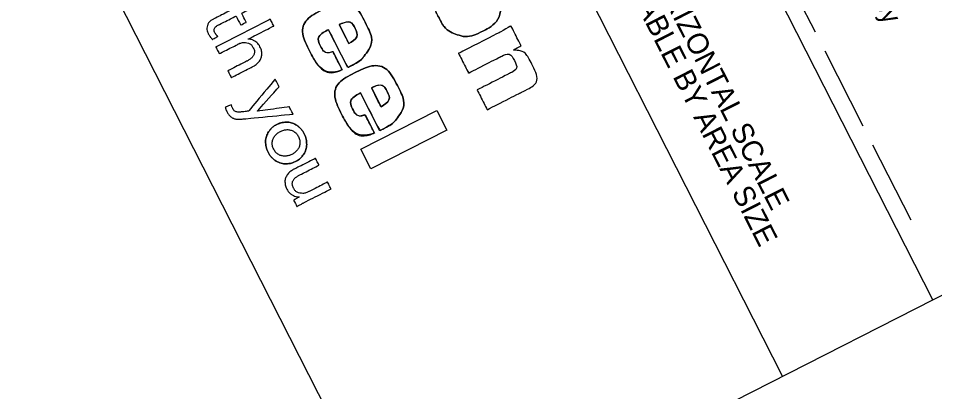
# Model space of a CAD drawing. Extents: x 152091 to 153435, y 1210118 to 1211616.
# Drawn here: x 152681.9 to 152812.3, y 1210201.4 to 1210254.5 of the extents above; entities that cross this region are included whole.
import ezdxf

# ---------------------------------------------------------------- set-up
doc = ezdxf.new("R2010")
doc.units = 0
for name, color, linetype in [('G-ANNO-BAR', 7, 'Continuous'), ('G-ANNO-STMP', 7, 'Continuous'), ('G-TTLB-LOGO', 7, 'Continuous'), ('G-TTLB-OTLN', 7, 'Continuous')]:
    doc.layers.add(name, color=color, linetype=linetype)

msp = doc.modelspace()

# ---------------------------------------------------------------- linework, layer by layer
at = {"layer": 'G-ANNO-STMP'}
for p, q in [((152789.88, 1210263.28), (152795.33, 1210252.59)), ((152796.69, 1210249.92), (152802.13, 1210239.22)), ((152803.49, 1210236.55), (152808.93, 1210225.85))]:
    msp.add_line(p, q, dxfattribs=at)
at = {"layer": 'G-TTLB-LOGO'}
for p, q in [((152728.79, 1210247.52), (152726.05, 1210252.91)), ((152727.59, 1210253.65), (152728.96, 1210250.95)), ((152726.7, 1210249.81), (152728.03, 1210247.19)), ((152732.16, 1210244.66), (152733.54, 1210241.96)), ((152733.36, 1210238.54), (152730.62, 1210243.92)), ((152730.68, 1210235.92), (152741.48, 1210241.42)), ((152731.27, 1210240.82), (152732.61, 1210238.21)), ((152741.48, 1210241.42), (152742.91, 1210238.61)), ((152742.91, 1210238.61), (152732.11, 1210233.11)), ((152732.11, 1210233.11), (152730.68, 1210235.92))]:
    msp.add_line(p, q, dxfattribs=at)
msp.add_lwpolyline([(152741.48, 1210241.42), (152742.91, 1210238.61), (152732.11, 1210233.11), (152730.68, 1210235.92), (152741.48, 1210241.42)], dxfattribs=at)
for points in [[(152749.56, 1210258.95), (152750.8, 1210256.51), (152750.54, 1210253.99), (152747.88, 1210252.64), (152746.79, 1210252.08), (152745.52, 1210251.83), (152744.35, 1210252.21), (152743.41, 1210252.53), (152742.48, 1210253.22), (152741.7, 1210254.76), (152740.85, 1210256.42), (152740.71, 1210257.7), (152741.04, 1210258.79), (152741.42, 1210260.08), (152742.43, 1210260.86), (152743.34, 1210261.32), (152745.65, 1210262.49), (152748.04, 1210261.93), (152749.56, 1210258.95)], [(152749.56, 1210258.95), (152750.8, 1210256.51), (152750.54, 1210253.99), (152747.88, 1210252.64), (152746.79, 1210252.08), (152745.52, 1210251.83), (152744.35, 1210252.21), (152743.41, 1210252.53), (152742.48, 1210253.22), (152741.7, 1210254.76), (152741.52, 1210255.1), (152741.38, 1210255.43), (152741.26, 1210255.74)], [(152713.57, 1210253.56), (152713.57, 1210253.56), (152712.91, 1210254.86), (152712.91, 1210254.86), (152712.91, 1210254.86), (152710.38, 1210253.57), (152710.38, 1210253.57), (152710.09, 1210253.42), (152709.9, 1210253.26), (152709.83, 1210253.08), (152709.76, 1210252.91), (152709.79, 1210252.7), (152709.91, 1210252.46), (152709.96, 1210252.38), (152710.01, 1210252.29), (152710.09, 1210252.19), (152710.16, 1210252.1), (152710.23, 1210252.02), (152710.31, 1210251.96), (152710.31, 1210251.96), (152709.54, 1210251.52), (152709.54, 1210251.52), (152709.44, 1210251.62), (152709.34, 1210251.73), (152709.24, 1210251.86), (152709.15, 1210251.99), (152709.06, 1210252.13), (152708.98, 1210252.28), (152708.75, 1210252.74), (152708.7, 1210253.15), (152708.83, 1210253.52), (152708.96, 1210253.9), (152709.28, 1210254.21), (152709.78, 1210254.47), (152709.78, 1210254.47), (152712.42, 1210255.81), (152712.42, 1210255.81), (152712.42, 1210255.81), (152711.95, 1210256.75), (152711.95, 1210256.75), (152711.95, 1210256.75), (152712.74, 1210257.15), (152712.74, 1210257.15), (152712.74, 1210257.15), (152713.21, 1210256.21), (152713.21, 1210256.21), (152713.21, 1210256.21), (152714.61, 1210256.92), (152714.61, 1210256.92), (152714.61, 1210256.92), (152715.1, 1210255.97), (152715.1, 1210255.97), (152715.1, 1210255.97), (152713.7, 1210255.26), (152713.7, 1210255.26), (152713.7, 1210255.26), (152714.36, 1210253.97), (152714.36, 1210253.97), (152714.36, 1210253.97), (152713.57, 1210253.56), (152713.57, 1210253.56)], [(152713.57, 1210253.56), (152713.57, 1210253.56), (152712.91, 1210254.86), (152712.91, 1210254.86), (152712.91, 1210254.86), (152710.38, 1210253.57), (152710.38, 1210253.57), (152710.09, 1210253.42), (152709.9, 1210253.26), (152709.83, 1210253.08), (152709.76, 1210252.91), (152709.79, 1210252.7), (152709.91, 1210252.46), (152709.96, 1210252.38), (152710.01, 1210252.29), (152710.09, 1210252.19), (152710.16, 1210252.1), (152710.23, 1210252.02), (152710.31, 1210251.96), (152710.31, 1210251.96), (152709.54, 1210251.52), (152709.54, 1210251.52), (152709.44, 1210251.62), (152709.34, 1210251.73), (152709.24, 1210251.86), (152709.15, 1210251.99), (152709.06, 1210252.13), (152708.98, 1210252.28), (152708.75, 1210252.74), (152708.7, 1210253.15), (152708.83, 1210253.52), (152708.96, 1210253.9), (152709.28, 1210254.21), (152709.78, 1210254.47), (152709.78, 1210254.47), (152712.42, 1210255.81), (152712.42, 1210255.81), (152712.42, 1210255.81), (152711.95, 1210256.75), (152711.95, 1210256.75), (152711.95, 1210256.75), (152712.74, 1210257.15), (152712.74, 1210257.15), (152712.74, 1210257.15), (152713.21, 1210256.21), (152713.21, 1210256.21), (152713.21, 1210256.21), (152714.61, 1210256.92), (152714.61, 1210256.92), (152714.61, 1210256.92), (152715.1, 1210255.97), (152715.1, 1210255.97), (152715.1, 1210255.97), (152713.7, 1210255.26), (152713.7, 1210255.26), (152713.7, 1210255.26), (152714.36, 1210253.97), (152714.36, 1210253.97), (152714.36, 1210253.97), (152713.57, 1210253.56), (152713.57, 1210253.56)], [(152726.05, 1210252.91), (152725.64, 1210252.7), (152724.22, 1210251.98), (152724.95, 1210250.54), (152725.33, 1210249.79), (152725.96, 1210249.53), (152726.7, 1210249.81), (152726.7, 1210249.81), (152728.03, 1210247.19), (152728.03, 1210247.19), (152726.04, 1210246.45), (152724.41, 1210247.84), (152723.42, 1210249.78), (152722.09, 1210252.4), (152722.69, 1210254.47), (152725.17, 1210255.74), (152727.68, 1210257.01), (152729.94, 1210256.62), (152731.35, 1210253.85), (152732.41, 1210251.76), (152732.05, 1210250.35), (152731.25, 1210249.3), (152730.77, 1210248.65), (152730.1, 1210248.19), (152728.79, 1210247.52), (152728.79, 1210247.52), (152726.05, 1210252.91), (152726.05, 1210252.91)], [(152728.03, 1210247.19), (152726.04, 1210246.45), (152724.41, 1210247.84), (152723.42, 1210249.78), (152722.09, 1210252.4), (152722.69, 1210254.47), (152725.17, 1210255.74), (152727.68, 1210257.01), (152729.94, 1210256.62), (152731.35, 1210253.85), (152732.41, 1210251.76), (152732.05, 1210250.35), (152731.25, 1210249.3), (152730.77, 1210248.65), (152730.1, 1210248.19), (152728.79, 1210247.52)], [(152714.65, 1210251.57), (152714.95, 1210251.57), (152715.25, 1210251.48), (152715.57, 1210251.28), (152715.88, 1210251.09), (152716.13, 1210250.82), (152716.31, 1210250.47), (152716.47, 1210250.16), (152716.55, 1210249.86), (152716.56, 1210249.58), (152716.57, 1210249.3), (152716.52, 1210249.04), (152716.42, 1210248.8), (152716.32, 1210248.55), (152716.17, 1210248.34), (152715.96, 1210248.14), (152715.76, 1210247.95), (152715.52, 1210247.78), (152715.25, 1210247.64), (152715.25, 1210247.64), (152712.23, 1210246.11), (152712.23, 1210246.11), (152712.23, 1210246.11), (152711.74, 1210247.07), (152711.74, 1210247.07), (152711.74, 1210247.07), (152714.43, 1210248.44), (152714.43, 1210248.44), (152714.63, 1210248.55), (152714.81, 1210248.66), (152714.98, 1210248.78), (152715.14, 1210248.9), (152715.27, 1210249.04), (152715.36, 1210249.19), (152715.46, 1210249.34), (152715.51, 1210249.51), (152715.52, 1210249.69), (152715.54, 1210249.87), (152715.48, 1210250.08), (152715.37, 1210250.3), (152715.17, 1210250.69), (152714.87, 1210250.93), (152714.45, 1210251.03), (152714.03, 1210251.12), (152713.58, 1210251.05), (152713.09, 1210250.8), (152713.09, 1210250.8), (152710.51, 1210249.49), (152710.51, 1210249.49), (152710.51, 1210249.49), (152710.02, 1210250.45), (152710.02, 1210250.45), (152710.02, 1210250.45), (152717.78, 1210254.4), (152717.78, 1210254.4), (152717.78, 1210254.4), (152718.27, 1210253.44), (152718.27, 1210253.44), (152718.27, 1210253.44), (152714.64, 1210251.59), (152714.64, 1210251.59), (152714.64, 1210251.59), (152714.65, 1210251.57), (152714.65, 1210251.57)], [(152714.65, 1210251.57), (152714.95, 1210251.57), (152715.25, 1210251.48), (152715.57, 1210251.28), (152715.88, 1210251.09), (152716.13, 1210250.82), (152716.31, 1210250.47), (152716.47, 1210250.16), (152716.55, 1210249.86), (152716.56, 1210249.58), (152716.57, 1210249.3), (152716.52, 1210249.04), (152716.42, 1210248.8), (152716.32, 1210248.55), (152716.17, 1210248.34), (152715.96, 1210248.14), (152715.76, 1210247.95), (152715.52, 1210247.78), (152715.25, 1210247.64), (152715.25, 1210247.64), (152712.23, 1210246.11), (152712.23, 1210246.11), (152712.23, 1210246.11), (152711.74, 1210247.07), (152711.74, 1210247.07), (152711.74, 1210247.07), (152714.43, 1210248.44), (152714.43, 1210248.44), (152714.63, 1210248.55), (152714.81, 1210248.66), (152714.98, 1210248.78), (152715.14, 1210248.9), (152715.27, 1210249.04), (152715.36, 1210249.19), (152715.46, 1210249.34), (152715.51, 1210249.51), (152715.52, 1210249.69), (152715.54, 1210249.87), (152715.48, 1210250.08), (152715.37, 1210250.3), (152715.17, 1210250.69), (152714.87, 1210250.93), (152714.45, 1210251.03), (152714.03, 1210251.12), (152713.58, 1210251.05), (152713.09, 1210250.8), (152713.09, 1210250.8), (152710.51, 1210249.49), (152710.51, 1210249.49), (152710.51, 1210249.49), (152710.02, 1210250.45), (152710.02, 1210250.45), (152710.02, 1210250.45), (152717.78, 1210254.4), (152717.78, 1210254.4), (152717.78, 1210254.4), (152718.27, 1210253.44), (152718.27, 1210253.44), (152718.27, 1210253.44), (152714.64, 1210251.59), (152714.64, 1210251.59), (152714.64, 1210251.59), (152714.65, 1210251.57), (152714.65, 1210251.57)], [(152728.96, 1210250.95), (152729.38, 1210251.2), (152730.47, 1210251.86), (152729.85, 1210253.09), (152729.23, 1210254.32), (152727.96, 1210253.8), (152727.59, 1210253.65), (152727.59, 1210253.65), (152728.96, 1210250.95), (152728.96, 1210250.95)], [(152728.96, 1210250.95), (152729.38, 1210251.2), (152730.47, 1210251.86), (152729.85, 1210253.09), (152729.23, 1210254.32), (152727.96, 1210253.8), (152727.59, 1210253.65)], [(152726.05, 1210252.91), (152725.64, 1210252.7), (152724.22, 1210251.98), (152724.95, 1210250.54), (152725.33, 1210249.79), (152725.96, 1210249.53), (152726.7, 1210249.81)], [(152750.48, 1210252.55), (152750.48, 1210252.55), (152752.04, 1210253.44), (152752.04, 1210253.44), (152752.04, 1210253.44), (152753.47, 1210250.63), (152753.47, 1210250.63), (152753.47, 1210250.63), (152752.34, 1210250.02), (152752.34, 1210250.02), (152753.08, 1210249.96), (152754.13, 1210249.74), (152754.92, 1210248.19), (152756.32, 1210245.44), (152754.23, 1210244.37), (152753.2, 1210243.85), (152753.2, 1210243.85), (152748.65, 1210241.53), (152748.65, 1210241.53), (152748.65, 1210241.53), (152747.22, 1210244.34), (152747.22, 1210244.34), (152747.22, 1210244.34), (152751.53, 1210246.54), (152751.53, 1210246.54), (152752.05, 1210246.8), (152753.11, 1210247.34), (152752.53, 1210248.49), (152751.89, 1210249.75), (152750.57, 1210249.08), (152750.3, 1210248.94), (152750.3, 1210248.94), (152746, 1210246.75), (152746, 1210246.75), (152746, 1210246.75), (152744.57, 1210249.55), (152744.57, 1210249.55), (152744.57, 1210249.55), (152750.48, 1210252.55), (152750.48, 1210252.55)], [(152750.48, 1210252.55), (152750.48, 1210252.55), (152752.04, 1210253.44), (152752.04, 1210253.44), (152752.04, 1210253.44), (152753.47, 1210250.63), (152753.47, 1210250.63), (152753.47, 1210250.63), (152752.34, 1210250.02), (152752.34, 1210250.02), (152753.08, 1210249.96), (152754.13, 1210249.74), (152754.92, 1210248.19), (152756.32, 1210245.44), (152754.23, 1210244.37), (152753.2, 1210243.85), (152753.2, 1210243.85), (152748.65, 1210241.53), (152748.65, 1210241.53), (152748.65, 1210241.53), (152747.22, 1210244.34), (152747.22, 1210244.34), (152747.22, 1210244.34), (152751.53, 1210246.54), (152751.53, 1210246.54), (152752.05, 1210246.8), (152753.11, 1210247.34), (152752.53, 1210248.49), (152751.89, 1210249.75), (152750.57, 1210249.08), (152750.3, 1210248.94), (152750.3, 1210248.94), (152746, 1210246.75), (152746, 1210246.75), (152746, 1210246.75), (152744.57, 1210249.55), (152744.57, 1210249.55), (152744.57, 1210249.55), (152750.48, 1210252.55), (152750.48, 1210252.55)], [(152730.62, 1210243.92), (152730.22, 1210243.71), (152728.8, 1210242.99), (152729.53, 1210241.55), (152729.91, 1210240.81), (152730.53, 1210240.54), (152731.27, 1210240.82), (152731.27, 1210240.82), (152732.61, 1210238.21), (152732.61, 1210238.21), (152730.61, 1210237.46), (152728.98, 1210238.85), (152727.99, 1210240.79), (152726.66, 1210243.41), (152727.26, 1210245.49), (152729.74, 1210246.75), (152732.26, 1210248.03), (152734.51, 1210247.63), (152735.92, 1210244.86), (152736.99, 1210242.77), (152736.63, 1210241.37), (152735.82, 1210240.32), (152735.35, 1210239.66), (152734.68, 1210239.21), (152733.36, 1210238.54), (152733.36, 1210238.54), (152730.62, 1210243.92), (152730.62, 1210243.92)], [(152732.61, 1210238.21), (152730.61, 1210237.46), (152728.98, 1210238.85), (152727.99, 1210240.79), (152726.66, 1210243.41), (152727.26, 1210245.49), (152729.74, 1210246.75), (152732.26, 1210248.03), (152734.51, 1210247.63), (152735.92, 1210244.86), (152736.99, 1210242.77), (152736.63, 1210241.37), (152735.82, 1210240.32), (152735.35, 1210239.66), (152734.68, 1210239.21), (152733.36, 1210238.54)], [(152715.97, 1210241.35), (152715.97, 1210241.35), (152715.98, 1210241.33), (152715.98, 1210241.33), (152715.98, 1210241.33), (152720.49, 1210241.93), (152720.49, 1210241.93), (152720.49, 1210241.93), (152721.01, 1210240.9), (152721.01, 1210240.9), (152721.01, 1210240.9), (152713.79, 1210240.2), (152713.79, 1210240.2), (152713.54, 1210240.18), (152713.31, 1210240.17), (152713.1, 1210240.18), (152712.89, 1210240.2), (152712.7, 1210240.24), (152712.52, 1210240.31), (152712.34, 1210240.39), (152712.18, 1210240.5), (152712.03, 1210240.64), (152711.88, 1210240.78), (152711.74, 1210240.97), (152711.62, 1210241.21), (152711.57, 1210241.32), (152711.52, 1210241.42), (152711.47, 1210241.53), (152711.43, 1210241.64), (152711.39, 1210241.76), (152711.37, 1210241.89), (152711.37, 1210241.89), (152712.26, 1210242.23), (152712.26, 1210242.23), (152712.29, 1210242.04), (152712.35, 1210241.86), (152712.43, 1210241.7), (152712.56, 1210241.45), (152712.72, 1210241.3), (152712.93, 1210241.25), (152713.13, 1210241.19), (152713.39, 1210241.18), (152713.7, 1210241.21), (152713.7, 1210241.21), (152714.67, 1210241.32), (152714.67, 1210241.32), (152714.67, 1210241.32), (152718.47, 1210245.88), (152718.47, 1210245.88), (152718.47, 1210245.88), (152719.02, 1210244.8), (152719.02, 1210244.8), (152719.02, 1210244.8), (152715.97, 1210241.35), (152715.97, 1210241.35)], [(152715.97, 1210241.35), (152715.97, 1210241.35), (152715.98, 1210241.33), (152715.98, 1210241.33), (152715.98, 1210241.33), (152720.49, 1210241.93), (152720.49, 1210241.93), (152720.49, 1210241.93), (152721.01, 1210240.9), (152721.01, 1210240.9), (152721.01, 1210240.9), (152713.79, 1210240.2), (152713.79, 1210240.2), (152713.54, 1210240.18), (152713.31, 1210240.17), (152713.1, 1210240.18), (152712.89, 1210240.2), (152712.7, 1210240.24), (152712.52, 1210240.31), (152712.34, 1210240.39), (152712.18, 1210240.5), (152712.03, 1210240.64), (152711.88, 1210240.78), (152711.74, 1210240.97), (152711.62, 1210241.21), (152711.57, 1210241.32), (152711.52, 1210241.42), (152711.47, 1210241.53), (152711.43, 1210241.64), (152711.39, 1210241.76), (152711.37, 1210241.89), (152711.37, 1210241.89), (152712.26, 1210242.23), (152712.26, 1210242.23), (152712.29, 1210242.04), (152712.35, 1210241.86), (152712.43, 1210241.7), (152712.56, 1210241.45), (152712.72, 1210241.3), (152712.93, 1210241.25), (152713.13, 1210241.19), (152713.39, 1210241.18), (152713.7, 1210241.21), (152713.7, 1210241.21), (152714.67, 1210241.32), (152714.67, 1210241.32), (152714.67, 1210241.32), (152718.47, 1210245.88), (152718.47, 1210245.88), (152718.47, 1210245.88), (152719.02, 1210244.8), (152719.02, 1210244.8), (152719.02, 1210244.8), (152715.97, 1210241.35), (152715.97, 1210241.35)], [(152733.54, 1210241.96), (152733.96, 1210242.21), (152735.05, 1210242.88), (152734.42, 1210244.1), (152733.8, 1210245.33), (152732.54, 1210244.82), (152732.16, 1210244.66), (152732.16, 1210244.66), (152733.54, 1210241.96), (152733.54, 1210241.96)], [(152733.54, 1210241.96), (152733.96, 1210242.21), (152735.05, 1210242.88), (152734.42, 1210244.1), (152733.8, 1210245.33), (152732.54, 1210244.82), (152732.16, 1210244.66)], [(152730.62, 1210243.92), (152730.22, 1210243.71), (152728.8, 1210242.99), (152729.53, 1210241.55), (152729.91, 1210240.81), (152730.53, 1210240.54), (152731.27, 1210240.82)], [(152721.38, 1210234.17), (152721, 1210233.98), (152720.62, 1210233.87), (152720.24, 1210233.85), (152719.86, 1210233.82), (152719.49, 1210233.87), (152719.14, 1210233.99), (152718.79, 1210234.1), (152718.47, 1210234.29), (152718.18, 1210234.55), (152717.89, 1210234.81), (152717.65, 1210235.12), (152717.46, 1210235.49), (152717.28, 1210235.86), (152717.16, 1210236.24), (152717.13, 1210236.63), (152717.09, 1210237.01), (152717.13, 1210237.38), (152717.24, 1210237.73), (152717.35, 1210238.08), (152717.53, 1210238.4), (152717.77, 1210238.69), (152718.02, 1210238.99), (152718.33, 1210239.23), (152718.71, 1210239.42), (152719.09, 1210239.61), (152719.46, 1210239.72), (152719.84, 1210239.75), (152720.22, 1210239.77), (152720.59, 1210239.72), (152720.93, 1210239.61), (152721.27, 1210239.49), (152721.59, 1210239.3), (152721.88, 1210239.05), (152722.17, 1210238.79), (152722.41, 1210238.47), (152722.6, 1210238.1), (152722.79, 1210237.73), (152722.9, 1210237.36), (152722.94, 1210236.97), (152722.97, 1210236.58), (152722.94, 1210236.21), (152722.83, 1210235.86), (152722.73, 1210235.51), (152722.55, 1210235.19), (152722.31, 1210234.9), (152722.07, 1210234.61), (152721.76, 1210234.37), (152721.38, 1210234.17)], [(152721.38, 1210234.17), (152721, 1210233.98), (152720.62, 1210233.87), (152720.24, 1210233.85), (152719.86, 1210233.82), (152719.49, 1210233.87), (152719.14, 1210233.99), (152718.79, 1210234.1), (152718.47, 1210234.29), (152718.18, 1210234.55), (152717.89, 1210234.81), (152717.65, 1210235.12), (152717.46, 1210235.49), (152717.28, 1210235.86), (152717.16, 1210236.24), (152717.13, 1210236.63), (152717.09, 1210237.01), (152717.13, 1210237.38), (152717.24, 1210237.73), (152717.35, 1210238.08), (152717.53, 1210238.4), (152717.77, 1210238.69), (152718.02, 1210238.99), (152718.33, 1210239.23), (152718.71, 1210239.42), (152718.92, 1210239.53), (152719.12, 1210239.61), (152719.33, 1210239.66)], [(152719.33, 1210239.66), (152719.5, 1210239.71), (152719.67, 1210239.74), (152719.84, 1210239.75), (152720.22, 1210239.77), (152720.59, 1210239.72), (152720.93, 1210239.61), (152721.27, 1210239.49), (152721.59, 1210239.3), (152721.88, 1210239.05), (152722.17, 1210238.79), (152722.41, 1210238.47), (152722.6, 1210238.1), (152722.79, 1210237.73), (152722.9, 1210237.36), (152722.94, 1210236.97), (152722.97, 1210236.58), (152722.94, 1210236.21), (152722.83, 1210235.86), (152722.73, 1210235.51), (152722.55, 1210235.19), (152722.31, 1210234.9), (152722.07, 1210234.61), (152721.76, 1210234.37), (152721.38, 1210234.17)], [(152720.86, 1210235.18), (152721.09, 1210235.3), (152721.3, 1210235.44), (152721.47, 1210235.62), (152721.65, 1210235.8), (152721.78, 1210236), (152721.87, 1210236.22), (152721.96, 1210236.44), (152722, 1210236.68), (152722, 1210236.93), (152721.99, 1210237.18), (152721.92, 1210237.43), (152721.79, 1210237.7), (152721.65, 1210237.96), (152721.49, 1210238.17), (152721.29, 1210238.32), (152721.09, 1210238.47), (152720.88, 1210238.58), (152720.64, 1210238.63), (152720.41, 1210238.69), (152720.18, 1210238.7), (152719.93, 1210238.66), (152719.68, 1210238.63), (152719.44, 1210238.55), (152719.21, 1210238.43), (152718.97, 1210238.31), (152718.77, 1210238.17), (152718.6, 1210237.99), (152718.42, 1210237.81), (152718.29, 1210237.61), (152718.19, 1210237.39), (152718.1, 1210237.16), (152718.05, 1210236.93), (152718.06, 1210236.68), (152718.07, 1210236.43), (152718.14, 1210236.17), (152718.27, 1210235.91), (152718.41, 1210235.65), (152718.57, 1210235.44), (152718.77, 1210235.29), (152718.97, 1210235.13), (152719.19, 1210235.03), (152719.42, 1210234.97), (152719.65, 1210234.92), (152719.89, 1210234.91), (152720.14, 1210234.95), (152720.39, 1210234.98), (152720.63, 1210235.06), (152720.86, 1210235.18)], [(152720.86, 1210235.18), (152721.09, 1210235.3), (152721.3, 1210235.44), (152721.47, 1210235.62), (152721.65, 1210235.8), (152721.78, 1210236), (152721.87, 1210236.22), (152721.96, 1210236.44), (152722, 1210236.68), (152722, 1210236.93), (152721.99, 1210237.18), (152721.92, 1210237.43), (152721.79, 1210237.7), (152721.65, 1210237.96), (152721.49, 1210238.17), (152721.29, 1210238.32), (152721.09, 1210238.47), (152720.88, 1210238.58), (152720.64, 1210238.63), (152720.41, 1210238.69), (152720.18, 1210238.7), (152719.93, 1210238.66), (152719.68, 1210238.63), (152719.44, 1210238.55), (152719.21, 1210238.43), (152718.97, 1210238.31), (152718.77, 1210238.17), (152718.6, 1210237.99), (152718.42, 1210237.81), (152718.29, 1210237.61), (152718.19, 1210237.39), (152718.1, 1210237.16), (152718.05, 1210236.93), (152718.06, 1210236.68), (152718.07, 1210236.43), (152718.14, 1210236.17), (152718.27, 1210235.91), (152718.41, 1210235.65), (152718.57, 1210235.44), (152718.77, 1210235.29), (152718.97, 1210235.13), (152719.19, 1210235.03), (152719.42, 1210234.97), (152719.65, 1210234.92), (152719.89, 1210234.91), (152720.14, 1210234.95), (152720.39, 1210234.98), (152720.63, 1210235.06), (152720.86, 1210235.18)], [(152721.11, 1210228.66), (152721.22, 1210228.74), (152721.36, 1210228.82), (152721.51, 1210228.91), (152721.66, 1210228.99), (152721.78, 1210229.06), (152721.89, 1210229.11), (152721.89, 1210229.11), (152721.88, 1210229.13), (152721.88, 1210229.13), (152721.55, 1210229.12), (152721.23, 1210229.22), (152720.9, 1210229.42), (152720.57, 1210229.62), (152720.31, 1210229.89), (152720.13, 1210230.25), (152719.97, 1210230.56), (152719.88, 1210230.86), (152719.87, 1210231.14), (152719.86, 1210231.43), (152719.9, 1210231.69), (152720.01, 1210231.93), (152720.12, 1210232.17), (152720.27, 1210232.38), (152720.47, 1210232.58), (152720.68, 1210232.77), (152720.92, 1210232.94), (152721.19, 1210233.08), (152721.19, 1210233.08), (152724.21, 1210234.61), (152724.21, 1210234.61), (152724.21, 1210234.61), (152724.7, 1210233.65), (152724.7, 1210233.65), (152724.7, 1210233.65), (152722.01, 1210232.28), (152722.01, 1210232.28), (152721.81, 1210232.18), (152721.63, 1210232.06), (152721.46, 1210231.94), (152721.3, 1210231.82), (152721.17, 1210231.68), (152721.07, 1210231.53), (152720.98, 1210231.38), (152720.92, 1210231.21), (152720.91, 1210231.02), (152720.91, 1210230.84), (152720.96, 1210230.63), (152721.07, 1210230.41), (152721.27, 1210230.02), (152721.58, 1210229.77), (152721.99, 1210229.68), (152722.4, 1210229.59), (152722.85, 1210229.67), (152723.34, 1210229.92), (152723.34, 1210229.92), (152725.93, 1210231.23), (152725.93, 1210231.23), (152725.93, 1210231.23), (152726.42, 1210230.27), (152726.42, 1210230.27), (152726.42, 1210230.27), (152722.6, 1210228.32), (152722.6, 1210228.32), (152722.47, 1210228.26), (152722.3, 1210228.17), (152722.1, 1210228.06), (152721.9, 1210227.95), (152721.72, 1210227.84), (152721.57, 1210227.75), (152721.57, 1210227.75), (152721.11, 1210228.66), (152721.11, 1210228.66)], [(152721.11, 1210228.66), (152721.22, 1210228.74), (152721.36, 1210228.82), (152721.51, 1210228.91), (152721.66, 1210228.99), (152721.78, 1210229.06), (152721.89, 1210229.11), (152721.89, 1210229.11), (152721.88, 1210229.13), (152721.88, 1210229.13), (152721.55, 1210229.12), (152721.23, 1210229.22), (152720.9, 1210229.42), (152720.57, 1210229.62), (152720.31, 1210229.89), (152720.13, 1210230.25), (152719.97, 1210230.56), (152719.88, 1210230.86), (152719.87, 1210231.14), (152719.86, 1210231.43), (152719.9, 1210231.69), (152720.01, 1210231.93), (152720.12, 1210232.17), (152720.27, 1210232.38), (152720.47, 1210232.58), (152720.68, 1210232.77), (152720.92, 1210232.94), (152721.19, 1210233.08), (152721.19, 1210233.08), (152724.21, 1210234.61), (152724.21, 1210234.61), (152724.21, 1210234.61), (152724.7, 1210233.65), (152724.7, 1210233.65), (152724.7, 1210233.65), (152722.01, 1210232.28), (152722.01, 1210232.28), (152721.81, 1210232.18), (152721.63, 1210232.06), (152721.46, 1210231.94), (152721.3, 1210231.82), (152721.17, 1210231.68), (152721.07, 1210231.53), (152720.98, 1210231.38), (152720.92, 1210231.21), (152720.91, 1210231.02), (152720.91, 1210230.84), (152720.96, 1210230.63), (152721.07, 1210230.41), (152721.27, 1210230.02), (152721.58, 1210229.77), (152721.99, 1210229.68), (152722.4, 1210229.59), (152722.85, 1210229.67), (152723.34, 1210229.92), (152723.34, 1210229.92), (152725.93, 1210231.23), (152725.93, 1210231.23), (152725.93, 1210231.23), (152726.42, 1210230.27), (152726.42, 1210230.27), (152726.42, 1210230.27), (152722.6, 1210228.32), (152722.6, 1210228.32), (152722.47, 1210228.26), (152722.3, 1210228.17), (152722.1, 1210228.06), (152721.9, 1210227.95), (152721.72, 1210227.84), (152721.57, 1210227.75), (152721.57, 1210227.75), (152721.11, 1210228.66), (152721.11, 1210228.66)]]:
    msp.add_open_spline(points, degree=3, dxfattribs=at)
at = {"layer": 'G-TTLB-OTLN'}
for p, q in [((152812.08, 1210214.49), (152725.8, 1210384)), ((152790.69, 1210203.61), (152704.41, 1210373.12)), ((152737.22, 1210176.39), (152650.94, 1210345.9))]:
    msp.add_line(p, q, dxfattribs=at)
msp.add_lwpolyline([(152844.12, 1211557.41), (153380.41, 1210503.76), (152662.36, 1210138.29), (152126.07, 1211191.94)], close=True, dxfattribs=at)

# ---------------------------------------------------------------- texts
at = {"layer": 'G-ANNO-BAR'}
for s, p in [('VARIABLE BY AREA SIZE', (152765.59, 1210264.74)), ('HORIZONTAL SCALE ', (152770.95, 1210262.76))]:
    msp.add_text(s, height=3, rotation=296.9754, dxfattribs=at).set_placement(p)
at = {"layer": 'G-ANNO-STMP'}
msp.add_text('Approved by', height=2.7, rotation=296.975, dxfattribs=at).set_placement((152796.12, 1210271.58))

doc.saveas('drawing.dxf')
